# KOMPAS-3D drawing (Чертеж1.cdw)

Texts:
  Стандартные изделия
  Болт М10x1,25-6gx30.109.30ХГСА (S16) ГОСТ 7805-70
  Гайка  М10x1,25-6H.04 (S16) ГОСТ 5915-70
  Шайба 10Л БрКМц3-1 ГОСТ 6402-70
  Болт М18x1,5-6gx55.109.30ХГСА ГОСТ 7805-70
  Болт М10x1,25-6gx25.109.30ХГСА (S16) ГОСТ 7805-70
  Болт М10x1,25-6gx35.109.30ХГСА (S16) ГОСТ 7805-70
  Болт М18x1,5-6gx20.109.30ХГСА ГОСТ 7805-70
